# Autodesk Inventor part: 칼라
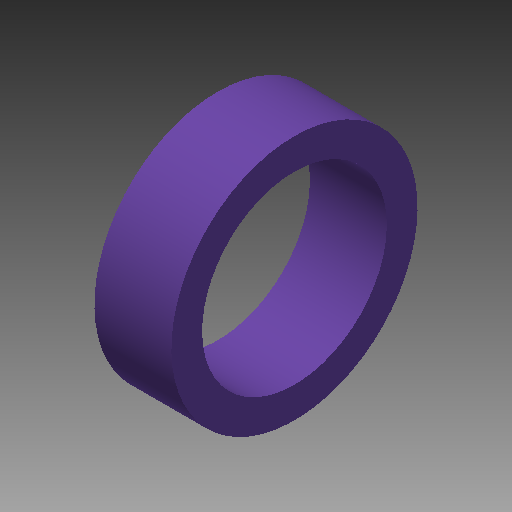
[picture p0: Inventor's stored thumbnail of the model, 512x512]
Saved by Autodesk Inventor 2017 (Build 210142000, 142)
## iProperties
Created: 2020-04
Part Number: 칼라
Material: 강철, 연강
Document SubType Name: Modeling
Designer: mduedu
Density: 7.86 g/cm^3
Appearance: 보라색
Mass: 3.45701 g
Surface Area: 6.15752 cm^2
Volume: 0.439823 cm^3
Author: mduedu
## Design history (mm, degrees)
sketch "스케치1"
  geometry: C1 r 8 at (0, 0); C2 r 6 at (0, 0); 1 further point
  constraints: 2 centre point, 2 coincident
  dimensions: "d0" = 16 diameter of C1; "d1" = 12 diameter of C2
extrude "돌출1" new body sketch "스케치1" distance "d2" = 5; taper "d3" = 0 deg
node "솔리드1"
